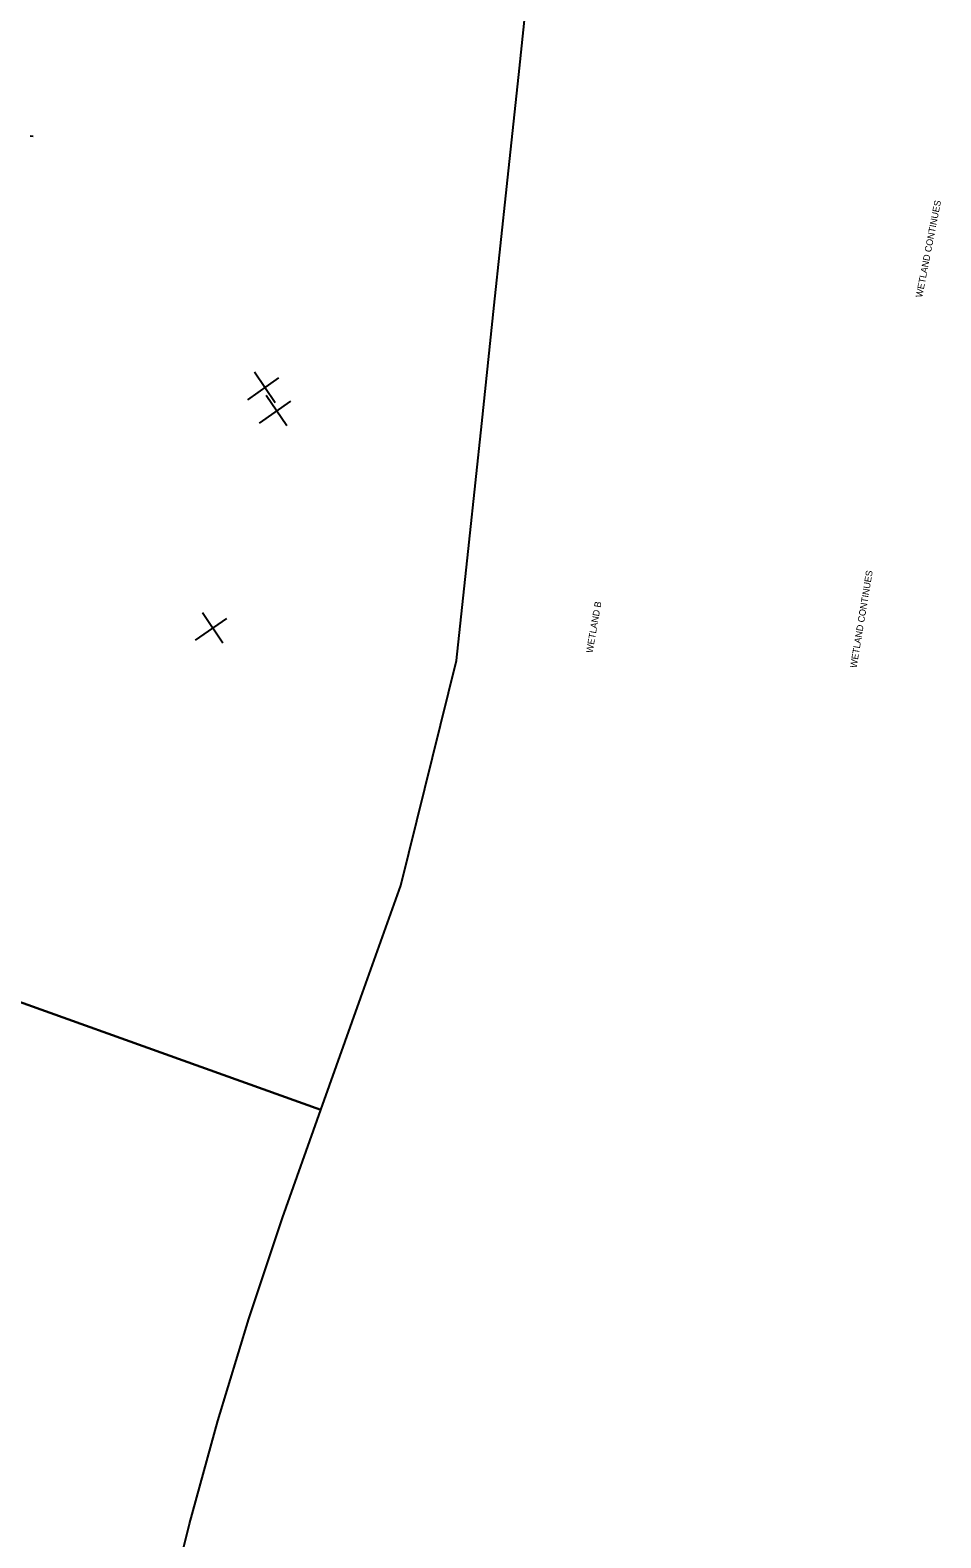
# Model space of a CAD drawing. Extents: x 172043 to 172958, y 249504 to 260295.
# Drawn here: x 172575 to 172958, y 255155 to 255788 of the extents above; entities that cross this region are included whole.
import ezdxf

# ---------------------------------------------------------------- set-up
doc = ezdxf.new("R2010")
doc.units = 0
for name, color, linetype in [('BD_X_Building', 7, 'Continuous'), ('DR_X_Storm_Sewer', 7, 'Continuous'), ('LT_X_Poles', 7, 'Continuous'), ('RW_X_CL_100_Stations', 7, 'Continuous')]:
    doc.layers.add(name, color=color, linetype=linetype)

msp = doc.modelspace()

# ---------------------------------------------------------------- linework, layer by layer
at = {"layer": 'BD_X_Building'}
for p, q in [((172666.74, 255632.58), (172679.84, 255641.72)), ((172678.25, 255631.36), (172669.59, 255644.11)), ((172671.66, 255622.83), (172684.76, 255631.97)), ((172683.17, 255621.61), (172674.52, 255634.36)), ((172644.79, 255531.66), (172657.89, 255540.79)), ((172656.3, 255530.44), (172647.65, 255543.19))]:
    msp.add_line(p, q, dxfattribs=at)
at = {"layer": 'DR_X_Storm_Sewer'}
for points in [[(172320.75, 255469.43), (172697.36, 255334.65), (172714.21, 255381.73), (172731.06, 255428.8), (172754.44, 255523.13), (172759.7, 255572.85), (172764.97, 255622.58), (172770.23, 255672.3), (172775.5, 255722.02), (172780.76, 255771.74), (172786.03, 255821.46), (172791.29, 255871.19), (172393.52, 255913.31), (172388.25, 255863.59), (172382.99, 255813.87), (172377.72, 255764.14), (172372.46, 255714.42), (172367.19, 255664.7), (172361.93, 255614.98), (172356.66, 255565.26), (172354.45, 255563.58), (172337.6, 255516.51)], [(172184.15, 254963.66), (172574.32, 254875.56), (172585.22, 254922.95), (172596.48, 254970.85), (172608.01, 255019.19), (172619.62, 255067.83), (172631.23, 255116.46), (172642.23, 255160.89), (172654.11, 255204.05), (172667.12, 255246.88), (172681.24, 255289.36), (172697.36, 255334.65), (172320.75, 255469.43), (172303.35, 255420.51), (172285.92, 255368.09), (172269.88, 255315.24), (172255.22, 255261.99), (172242.17, 255209.36), (172230.56, 255160.73), (172218.95, 255112.1), (172207.28, 255063.17), (172195.65, 255013.72)]]:
    msp.add_lwpolyline(points, close=True, dxfattribs=at)
at = {"layer": 'RW_X_CL_100_Stations'}
msp.add_line((172576.61, 255743.08), (172575.42, 255743.21), dxfattribs=at)

# ---------------------------------------------------------------- texts
at = {"layer": 'LT_X_Poles'}
for s, height, rotation, p in [('WETLAND CONTINUES', 2.8003, 78.92184, (172949.91, 255675.32)), ('WETLAND CONTINUES', 2.8003, 80.50961, (172922.36, 255519.89)), ('WETLAND B', 2.8, 79.91498, (172811.47, 255526.18))]:
    msp.add_text(s, height=height, rotation=rotation, dxfattribs=at).set_placement(p)

doc.saveas('drawing.dxf')
